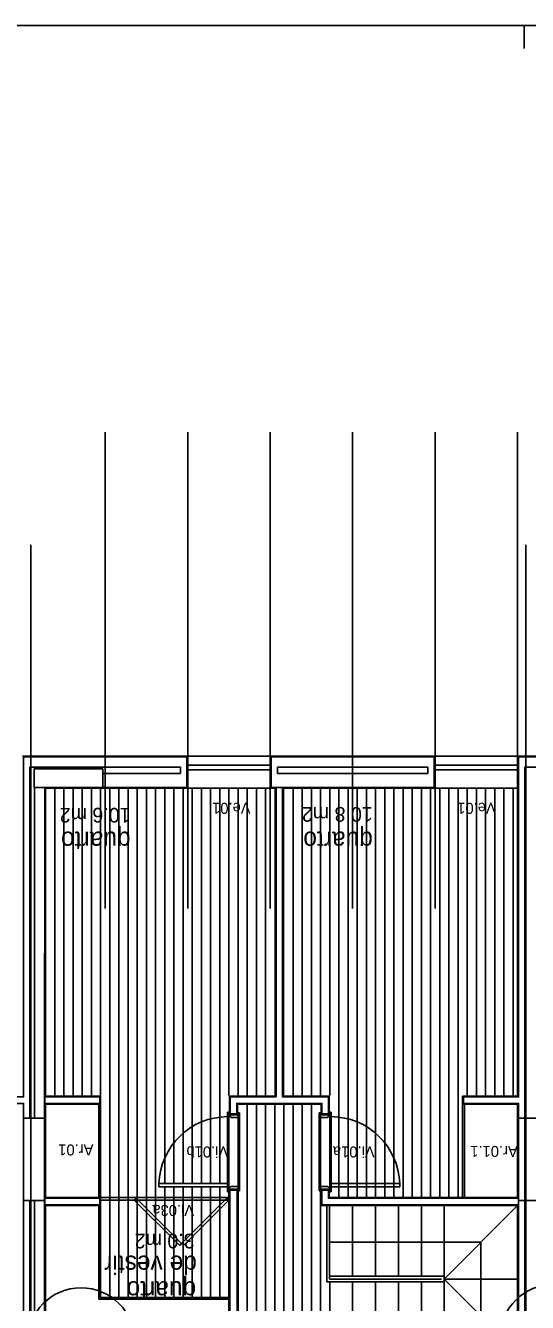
# Model space of a CAD drawing. Extents: x 1278 to 1356, y -253.7 to -224.
# Drawn here: x 1340.02 to 1345.5, y -237.88 to -223.96 of the extents above; entities that cross this region are included whole.
import ezdxf

# ---------------------------------------------------------------- set-up
doc = ezdxf.new("R2010")
doc.units = 0
for name, color, linetype in [('Level 1', 7, 'Continuous'), ('Level 10', 7, 'Continuous'), ('Level 13', 7, 'Continuous'), ('Level 2', 7, 'Continuous'), ('Level 4', 7, 'Continuous'), ('Level 40', 7, 'Continuous'), ('Level 60', 7, 'Continuous'), ('Level 62', 7, 'Continuous'), ('Level 65', 7, 'Continuous'), ('Level 66', 7, 'Continuous'), ('Level 67', 7, 'Continuous'), ('Level 69', 7, 'Continuous'), ('Level 70', 7, 'Continuous'), ('Level 93', 7, 'Continuous')]:
    doc.layers.add(name, color=color, linetype=linetype)

msp = doc.modelspace()

# ---------------------------------------------------------------- linework, layer by layer
at = {"layer": 'Level 1'}
for p, q in [((1341.784, -231.934), (1341.784, -232.266)), ((1342.704, -232.266), (1342.704, -231.934)), ((1344.484, -231.934), (1344.484, -232.266)), ((1347.184, -231.934), (1345.404, -231.934)), ((1345.404, -235.641), (1345.404, -231.934)), ((1340.073, -232.044), (1340.073, -235.871)), ((1341.714, -232.044), (1341.714, -232.114)), ((1342.774, -232.114), (1342.774, -232.044)), ((1344.414, -232.044), (1344.414, -232.114)), ((1347.114, -232.044), (1345.474, -232.044)), ((1345.474, -232.044), (1345.474, -240.304)), ((1345.474, -232.114), (1345.474, -232.044)), ((1341.714, -232.114), (1340.868, -232.114)), ((1340.234, -246.584), (1340.234, -232.266)), ((1341.784, -232.266), (1340.234, -232.266)), ((1344.484, -232.266), (1342.704, -232.266)), ((1342.759, -232.266), (1342.759, -235.641)), ((1342.829, -235.641), (1342.829, -232.266)), ((1340.834, -235.641), (1340.234, -235.641)), ((1340.834, -235.711), (1340.834, -235.641)), ((1342.759, -235.641), (1342.259, -235.641)), ((1342.259, -235.641), (1342.259, -235.826)), ((1343.329, -235.641), (1342.829, -235.641)), ((1343.329, -235.826), (1343.329, -235.641)), ((1345.404, -235.641), (1344.804, -235.641)), ((1344.804, -235.641), (1344.804, -235.711)), ((1340.234, -235.711), (1340.834, -235.711)), ((1342.249, -235.826), (1342.339, -235.826)), ((1342.329, -235.711), (1343.259, -235.711)), ((1342.329, -235.826), (1342.329, -235.711)), ((1343.339, -235.826), (1343.249, -235.826)), ((1343.259, -235.711), (1343.259, -235.826)), ((1344.804, -235.711), (1345.404, -235.711)), ((1345.404, -236.746), (1345.404, -235.711)), ((1342.244, -236.656), (1342.344, -236.656)), ((1342.254, -236.656), (1342.254, -238.436)), ((1342.334, -238.436), (1342.334, -236.656)), ((1343.339, -236.656), (1343.249, -236.656)), ((1343.259, -236.656), (1343.259, -236.816)), ((1343.329, -236.656), (1343.329, -236.746)), ((1340.073, -236.771), (1340.073, -242.171)), ((1340.124, -242.171), (1340.124, -236.771)), ((1340.834, -236.746), (1340.234, -236.746)), ((1340.234, -236.816), (1340.834, -236.816)), ((1340.834, -236.816), (1340.834, -236.746)), ((1343.259, -236.816), (1345.404, -236.816)), ((1343.329, -236.746), (1345.404, -236.746)), ((1345.404, -238.436), (1345.404, -236.816))]:
    msp.add_line(p, q, dxfattribs=at)
at = {"layer": 'Level 10'}
for p, q in [((1340.344, -232.276), (1340.344, -235.631)), ((1340.444, -232.276), (1340.444, -235.631)), ((1340.544, -232.276), (1340.544, -235.631)), ((1340.644, -232.276), (1340.644, -235.631)), ((1340.744, -232.276), (1340.744, -235.631)), ((1340.844, -232.276), (1340.844, -235.626)), ((1340.944, -232.276), (1340.944, -237.826)), ((1341.044, -232.276), (1341.044, -237.826)), ((1341.144, -232.276), (1341.144, -237.826)), ((1341.244, -232.276), (1341.244, -237.826)), ((1341.344, -232.276), (1341.344, -237.826)), ((1341.444, -232.276), (1341.444, -237.826)), ((1341.544, -232.276), (1341.544, -236.586)), ((1341.644, -232.276), (1341.644, -236.586)), ((1341.744, -232.276), (1341.744, -236.586)), ((1341.844, -232.276), (1341.844, -236.586)), ((1341.944, -232.276), (1341.944, -236.586)), ((1342.044, -232.276), (1342.044, -236.586)), ((1342.144, -232.276), (1342.144, -236.586)), ((1342.244, -232.276), (1342.244, -235.626)), ((1342.344, -232.276), (1342.344, -235.626)), ((1342.444, -232.276), (1342.444, -235.626)), ((1342.544, -232.276), (1342.544, -235.626)), ((1342.644, -232.276), (1342.644, -235.626)), ((1342.944, -235.626), (1342.944, -232.276)), ((1343.044, -235.626), (1343.044, -232.276)), ((1343.144, -235.626), (1343.144, -232.276)), ((1343.244, -235.626), (1343.244, -232.276)), ((1343.344, -235.626), (1343.344, -232.276)), ((1343.444, -232.276), (1343.444, -236.736)), ((1343.544, -232.276), (1343.544, -236.736)), ((1343.644, -232.276), (1343.644, -236.736)), ((1343.744, -232.276), (1343.744, -236.736)), ((1343.844, -232.276), (1343.844, -236.736)), ((1343.944, -232.276), (1343.944, -236.736)), ((1344.044, -232.276), (1344.044, -236.736)), ((1344.144, -232.276), (1344.144, -236.736)), ((1344.244, -232.276), (1344.244, -236.736)), ((1344.344, -232.276), (1344.344, -236.736)), ((1344.444, -232.276), (1344.444, -236.736)), ((1344.544, -232.276), (1344.544, -236.736)), ((1344.644, -232.276), (1344.644, -236.736)), ((1344.744, -232.276), (1344.744, -236.736)), ((1344.844, -232.276), (1344.844, -235.626)), ((1344.944, -232.276), (1344.944, -235.626)), ((1345.044, -232.276), (1345.044, -235.626)), ((1345.144, -232.276), (1345.144, -235.626)), ((1345.244, -232.276), (1345.244, -235.626)), ((1345.344, -232.276), (1345.344, -235.626)), ((1342.444, -235.721), (1342.444, -238.411)), ((1342.544, -235.721), (1342.544, -238.426)), ((1342.644, -235.721), (1342.644, -238.426)), ((1342.744, -235.721), (1342.744, -238.426)), ((1342.844, -235.721), (1342.844, -238.426)), ((1342.944, -235.721), (1342.944, -238.426)), ((1343.044, -235.721), (1343.044, -238.426)), ((1343.144, -235.721), (1343.144, -238.411)), ((1342.244, -235.856), (1342.244, -236.626)), ((1342.344, -235.866), (1342.344, -236.616)), ((1343.244, -235.866), (1343.244, -236.616)), ((1343.344, -235.856), (1343.344, -236.626)), ((1341.544, -236.621), (1341.544, -237.826)), ((1341.644, -236.621), (1341.644, -237.826)), ((1341.744, -236.621), (1341.744, -237.826)), ((1341.844, -236.621), (1341.844, -237.826)), ((1341.944, -236.621), (1341.944, -237.826)), ((1342.044, -236.621), (1342.044, -237.826)), ((1342.144, -236.621), (1342.144, -237.826)), ((1343.244, -236.656), (1343.244, -238.426))]:
    msp.add_line(p, q, dxfattribs=at)
at = {"layer": 'Level 13'}
for p, q in [((1340.824, -236.736), (1340.824, -235.721)), ((1340.844, -236.736), (1340.844, -235.721)), ((1342.229, -235.806), (1342.229, -235.856)), ((1342.239, -235.806), (1342.229, -235.806)), ((1342.239, -235.811), (1342.239, -235.806)), ((1342.244, -235.811), (1342.239, -235.811)), ((1342.244, -235.856), (1342.244, -235.811)), ((1342.244, -235.836), (1342.344, -235.836)), ((1342.244, -235.856), (1342.244, -235.836)), ((1342.344, -235.866), (1342.344, -235.821)), ((1342.344, -235.821), (1342.349, -235.821)), ((1342.344, -235.836), (1342.344, -235.866)), ((1342.349, -235.821), (1342.349, -235.816)), ((1342.349, -235.816), (1342.359, -235.816)), ((1342.359, -235.816), (1342.359, -235.866)), ((1343.229, -235.816), (1343.229, -235.866)), ((1343.239, -235.816), (1343.229, -235.816)), ((1343.239, -235.821), (1343.239, -235.816)), ((1343.244, -235.821), (1343.239, -235.821)), ((1343.244, -235.866), (1343.244, -235.821)), ((1343.344, -235.836), (1343.244, -235.836)), ((1343.244, -235.836), (1343.244, -235.866)), ((1343.344, -235.856), (1343.344, -235.811)), ((1343.344, -235.811), (1343.349, -235.811)), ((1343.344, -235.856), (1343.344, -235.836)), ((1343.349, -235.811), (1343.349, -235.806)), ((1343.349, -235.806), (1343.359, -235.806)), ((1343.359, -235.806), (1343.359, -235.856)), ((1344.794, -236.736), (1344.794, -235.721)), ((1344.814, -236.736), (1344.814, -235.721)), ((1342.229, -235.856), (1342.244, -235.856)), ((1342.264, -235.856), (1342.244, -235.856)), ((1342.264, -235.866), (1342.264, -235.856)), ((1342.344, -235.866), (1342.264, -235.866)), ((1342.359, -235.866), (1342.344, -235.866)), ((1343.229, -235.866), (1343.244, -235.866)), ((1343.244, -235.866), (1343.324, -235.866)), ((1343.324, -235.866), (1343.324, -235.856)), ((1343.324, -235.856), (1343.344, -235.856)), ((1343.359, -235.856), (1343.344, -235.856)), ((1342.229, -236.586), (1341.479, -236.586)), ((1341.479, -236.586), (1341.479, -236.621)), ((1341.479, -236.621), (1342.229, -236.621)), ((1342.229, -236.621), (1342.229, -236.586)), ((1342.229, -236.676), (1342.229, -236.626)), ((1342.229, -236.626), (1342.244, -236.626)), ((1342.239, -236.676), (1342.229, -236.676)), ((1342.244, -236.671), (1342.239, -236.671)), ((1342.239, -236.671), (1342.239, -236.676)), ((1342.264, -236.626), (1342.244, -236.626)), ((1342.244, -236.626), (1342.244, -236.646)), ((1342.244, -236.626), (1342.244, -236.671)), ((1342.244, -236.646), (1342.344, -236.646)), ((1342.344, -236.616), (1342.264, -236.616)), ((1342.264, -236.616), (1342.264, -236.626)), ((1342.344, -236.646), (1342.344, -236.616)), ((1342.359, -236.616), (1342.344, -236.616)), ((1342.344, -236.616), (1342.344, -236.661)), ((1342.344, -236.661), (1342.349, -236.661)), ((1342.349, -236.661), (1342.349, -236.666)), ((1342.349, -236.666), (1342.359, -236.666)), ((1342.359, -236.666), (1342.359, -236.616)), ((1343.229, -236.666), (1343.229, -236.616)), ((1343.229, -236.616), (1343.244, -236.616)), ((1343.239, -236.666), (1343.229, -236.666)), ((1343.244, -236.661), (1343.239, -236.661)), ((1343.239, -236.661), (1343.239, -236.666)), ((1343.244, -236.616), (1343.244, -236.661)), ((1343.244, -236.646), (1343.244, -236.616)), ((1343.244, -236.616), (1343.324, -236.616)), ((1343.344, -236.646), (1343.244, -236.646)), ((1343.324, -236.616), (1343.324, -236.626)), ((1343.324, -236.626), (1343.344, -236.626)), ((1343.344, -236.626), (1343.344, -236.646)), ((1343.359, -236.626), (1343.344, -236.626)), ((1343.344, -236.626), (1343.344, -236.671)), ((1343.344, -236.671), (1343.349, -236.671)), ((1343.349, -236.671), (1343.349, -236.676)), ((1343.349, -236.676), (1343.359, -236.676)), ((1343.359, -236.621), (1343.359, -236.586)), ((1343.359, -236.586), (1344.109, -236.586)), ((1344.109, -236.621), (1343.359, -236.621)), ((1343.359, -236.676), (1343.359, -236.626)), ((1344.109, -236.586), (1344.109, -236.621)), ((1341.212, -236.766), (1341.233, -236.745)), ((1341.212, -236.766), (1341.707, -237.261)), ((1341.233, -236.745), (1341.728, -237.24)), ((1342.223, -236.745), (1341.728, -237.24)), ((1342.244, -236.766), (1341.749, -237.261)), ((1342.244, -236.766), (1342.223, -236.745)), ((1340.824, -237.846), (1340.824, -236.826)), ((1340.844, -237.826), (1340.844, -236.826)), ((1341.707, -237.261), (1341.728, -237.24)), ((1341.749, -237.261), (1341.728, -237.24)), ((1342.244, -237.846), (1340.824, -237.846)), ((1342.244, -237.826), (1340.844, -237.826))]:
    msp.add_line(p, q, dxfattribs=at)
at = {"layer": 'Level 2'}
for p, q in [((1342.694, -231.924), (1341.794, -231.924)), ((1345.394, -231.924), (1344.494, -231.924)), ((1342.694, -232.024), (1341.794, -232.024)), ((1342.694, -232.074), (1341.794, -232.074)), ((1345.394, -232.024), (1344.494, -232.024)), ((1345.394, -232.074), (1344.494, -232.074)), ((1342.694, -232.276), (1341.794, -232.276)), ((1345.394, -232.276), (1344.494, -232.276)), ((1343.313, -237.656), (1343.313, -236.826)), ((1343.343, -237.626), (1343.343, -236.826)), ((1343.594, -237.596), (1343.594, -236.826)), ((1343.844, -237.596), (1343.844, -236.826)), ((1344.094, -237.596), (1344.094, -236.826)), ((1344.344, -237.596), (1344.344, -236.826)), ((1344.594, -237.596), (1344.594, -236.826)), ((1344.594, -237.626), (1345.394, -236.826)), ((1343.344, -237.226), (1344.994, -237.226)), ((1344.994, -238.026), (1344.994, -237.226)), ((1344.594, -237.596), (1343.344, -237.596)), ((1344.562, -237.626), (1343.344, -237.626)), ((1343.594, -238.424), (1343.594, -237.654)), ((1343.844, -238.424), (1343.844, -237.654)), ((1344.094, -237.654), (1344.094, -238.424)), ((1344.344, -237.654), (1344.344, -238.424)), ((1344.594, -237.656), (1344.594, -237.596)), ((1345.394, -237.626), (1344.594, -237.626)), ((1344.594, -237.626), (1345.394, -238.426)), ((1344.594, -237.656), (1343.313, -237.656)), ((1343.344, -238.424), (1343.344, -237.656)), ((1344.594, -238.426), (1344.594, -237.656))]:
    msp.add_line(p, q, dxfattribs=at)
at = {"layer": 'Level 4'}
for p, q in [((1342.229, -235.856), (1342.229, -236.586)), ((1342.359, -236.616), (1342.359, -235.866)), ((1343.229, -236.616), (1343.229, -235.866)), ((1343.359, -235.856), (1343.359, -236.586)), ((1340.844, -236.736), (1342.244, -236.736)), ((1340.844, -236.766), (1342.244, -236.766))]:
    msp.add_line(p, q, dxfattribs=at)
for centre, start_param, end_param in [((1342.229, -236.619), 3.141593, 4.668897), ((1343.359, -236.619), 1.614288, 3.141593)]:
    msp.add_ellipse(centre, major_axis=(0, -0.763), ratio=0.982661, start_param=start_param, end_param=end_param, dxfattribs=at)
at = {"layer": 'Level 62'}
msp.add_line((1345.466, -224.209), (1345.466, -223.959), dxfattribs=at)
msp.add_lwpolyline([(1355.966, -223.959), (1355.966, -253.659), (1278.016, -253.659), (1278.016, -223.959)], close=True, dxfattribs=at)
at = {"layer": 'Level 65'}
for p, q in [((1341.794, -231.924), (1339.993, -231.924)), ((1341.794, -231.924), (1341.794, -232.276)), ((1342.694, -232.276), (1342.694, -231.924)), ((1344.494, -231.924), (1342.694, -231.924)), ((1344.494, -231.924), (1344.494, -232.276)), ((1347.194, -231.924), (1345.394, -231.924)), ((1345.394, -235.631), (1345.394, -231.924)), ((1341.794, -232.276), (1340.244, -232.276)), ((1340.244, -235.631), (1340.244, -232.276)), ((1342.749, -232.276), (1342.694, -232.276)), ((1342.749, -232.276), (1342.749, -235.631)), ((1342.839, -235.631), (1342.839, -232.276)), ((1344.494, -232.276), (1342.839, -232.276)), ((1340.844, -235.631), (1340.244, -235.631)), ((1340.844, -235.721), (1340.844, -235.631)), ((1342.749, -235.631), (1342.249, -235.631)), ((1342.249, -235.631), (1342.249, -235.826)), ((1343.339, -235.631), (1342.839, -235.631)), ((1343.339, -235.826), (1343.339, -235.631)), ((1345.394, -235.631), (1344.794, -235.631)), ((1344.794, -235.631), (1344.794, -235.721)), ((1340.244, -236.736), (1340.244, -235.721)), ((1340.244, -235.721), (1340.844, -235.721)), ((1342.339, -235.826), (1342.339, -235.721)), ((1342.339, -235.721), (1343.249, -235.721)), ((1343.249, -235.721), (1343.249, -235.826)), ((1344.794, -235.721), (1345.394, -235.721)), ((1345.394, -236.736), (1345.394, -235.721)), ((1342.244, -236.656), (1342.244, -238.426)), ((1342.344, -238.426), (1342.344, -236.656)), ((1343.249, -236.656), (1343.249, -236.826)), ((1343.339, -236.656), (1343.339, -236.736)), ((1340.844, -236.736), (1340.244, -236.736)), ((1340.844, -236.826), (1340.844, -236.736)), ((1345.394, -236.736), (1343.339, -236.736)), ((1340.244, -236.826), (1340.844, -236.826)), ((1343.249, -236.826), (1345.394, -236.826)), ((1345.394, -238.426), (1345.394, -236.826))]:
    msp.add_line(p, q, dxfattribs=at)
msp.add_lwpolyline([(1340.244, -238.164), (1340.244, -236.826)], dxfattribs=at)
at = {"layer": 'Level 66'}
for p, q in [((1341.784, -231.934), (1340.003, -231.934)), ((1344.484, -231.934), (1342.704, -231.934)), ((1341.714, -232.044), (1340.073, -232.044)), ((1340.868, -232.064), (1340.118, -232.064)), ((1340.118, -232.064), (1340.118, -232.266)), ((1340.868, -232.114), (1340.868, -232.064)), ((1344.414, -232.044), (1342.774, -232.044)), ((1344.414, -232.114), (1342.774, -232.114)), ((1340.124, -235.871), (1340.124, -232.266))]:
    msp.add_line(p, q, dxfattribs=at)
for points in [[(1340.868, -232.064), (1340.118, -232.064), (1340.118, -232.266), (1340.868, -232.266)], [(1340.003, -235.871), (1340.233, -235.871), (1340.233, -236.771), (1340.003, -236.771)], [(1345.634, -236.771), (1345.404, -236.771), (1345.404, -235.871), (1345.634, -235.871)]]:
    msp.add_lwpolyline(points, close=True, dxfattribs=at)
at = {"layer": 'Level 67'}
for points in [[(1340.868, -232.114), (1340.868, -232.266), (1341.784, -232.266), (1341.784, -231.934), (1340.003, -231.934), (1340.003, -235.641), (1339.403, -235.641), (1339.403, -235.711), (1340.003, -235.711), (1340.003, -235.871), (1340.073, -235.871), (1340.073, -232.044), (1341.714, -232.044), (1341.714, -232.114)], [(1346.268, -232.264), (1346.268, -232.114), (1347.114, -232.114), (1347.114, -232.044), (1345.474, -232.044), (1345.474, -235.871), (1345.404, -235.871), (1345.404, -235.711), (1344.804, -235.711), (1344.804, -235.641), (1345.404, -235.641), (1345.404, -231.934), (1347.184, -231.934), (1347.184, -232.264)], [(1340.233, -235.871), (1340.124, -235.871), (1340.124, -232.266), (1340.118, -232.266), (1340.234, -232.266)], [(1342.829, -232.266), (1342.829, -235.641), (1343.329, -235.641), (1343.329, -235.826), (1343.259, -235.826), (1343.259, -235.711), (1342.329, -235.711), (1342.329, -235.826), (1342.259, -235.826), (1342.259, -235.641), (1342.759, -235.641), (1342.759, -232.266)], [(1340.834, -235.641), (1340.834, -235.711), (1340.234, -235.711), (1340.234, -235.641)], [(1345.404, -236.746), (1343.329, -236.746), (1343.329, -236.656), (1343.259, -236.656), (1343.259, -236.816), (1345.404, -236.816)], [(1340.073, -242.171), (1340.003, -242.171), (1340.003, -236.771), (1340.073, -236.771)], [(1340.233, -242.171), (1340.234, -242.171), (1340.234, -242.109), (1340.834, -242.109), (1340.834, -242.039), (1340.234, -242.039), (1340.233, -236.771), (1340.124, -236.771), (1340.124, -242.171), (1340.234, -242.171)], [(1340.834, -236.746), (1340.834, -236.816), (1340.234, -236.816), (1340.234, -236.746)]]:
    msp.add_lwpolyline(points, close=True, dxfattribs=at)
for points in [[(1342.254, -238.436), (1342.254, -236.656), (1342.334, -236.656), (1342.334, -238.436)], [(1345.404, -240.234), (1345.404, -236.771), (1345.474, -236.771), (1345.474, -240.304)]]:
    msp.add_lwpolyline(points, dxfattribs=at)
at = {"layer": 'Level 69'}
for centre in [(1340.631, -238.306), (1345.787, -238.268)]:
    msp.add_circle(centre, 0.584, dxfattribs=at)
at = {"layer": 'Level 70'}
for p, q in [((1340.084, -229.62), (1340.084, -250.792)), ((1345.484, -250.792), (1345.484, -229.62))]:
    msp.add_line(p, q, dxfattribs=at)
at = {"layer": 'Level 93'}
for p, q in [((1340.894, -233.587), (1340.894, -228.394)), ((1341.794, -233.587), (1341.794, -228.394)), ((1342.694, -233.587), (1342.694, -228.394)), ((1343.594, -233.587), (1343.594, -228.394)), ((1344.494, -233.587), (1344.494, -228.394)), ((1345.394, -233.587), (1345.394, -228.394))]:
    msp.add_line(p, q, dxfattribs=at)

# ---------------------------------------------------------------- texts
at = {"layer": 'Level 40'}
for s, p in [('Ve.01', (1342.48, -232.434)), ('Ve.01', (1345.155, -232.434)), ('Ar.01', (1340.766, -236.159)), ('Vi.01b', (1342.236, -236.181)), ('Vi.01a', (1343.834, -236.181)), ('Ar.01.1', (1345.395, -236.175)), ('Vi.03a', (1341.864, -236.819))]:
    msp.add_text(s, height=0.12, rotation=180, dxfattribs=at).set_placement(p)
at = {"layer": 'Level 60'}
for s, height, p in [('10.6 m2', 0.16, (1341.171, -232.489)), ('10.8 m2', 0.16, (1343.813, -232.48)), ('quarto', 0.2, (1341.171, -232.748)), ('quarto', 0.2, (1343.814, -232.748)), ('3.0 m2', 0.16, (1341.87, -237.132)), ('de vestir', 0.2, (1341.894, -237.371)), ('de vestir', 0.2, (1341.894, -237.371)), ('quarto', 0.2, (1341.886, -237.65))]:
    msp.add_text(s, height=height, rotation=180, dxfattribs=at).set_placement(p)

doc.saveas('drawing.dxf')
